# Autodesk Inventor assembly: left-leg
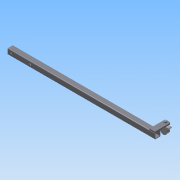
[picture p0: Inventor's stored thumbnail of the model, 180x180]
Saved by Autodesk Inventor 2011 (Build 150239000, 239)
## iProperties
Created: 2020-12
Part Number: left-leg
Document SubType Name: Weldment
Designer: PC
Weld Material: Welded Steel Mild
Author: PC
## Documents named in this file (4)
- C:\Users\PC\Documents\Inventor\workshop-crane-powered-by-drill\left-leg.iam
- C:\Users\PC\Documents\Inventor\workshop-crane-powered-by-drill\4_pata-izquierda.iam
- C:\Users\PC\Documents\Inventor\workshop-crane-powered-by-drill\wheel.ipt
- C:\Users\PC\Documents\Inventor\Content Center Files\R2011\en-US\DIN 555\DIN 555-5 - M14.ipt
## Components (3 placed, 3 different names)
1. 4_pata-izquierda:1 [sub-assembly] — Insert:1
2. wheel:1 — Insert:1
3. DIN 555 - replaced by DIN EN 24034 M14:1
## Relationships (1: Insert 1)
- Insert:1: 4_pata-izquierda:1 ↔ wheel:1
